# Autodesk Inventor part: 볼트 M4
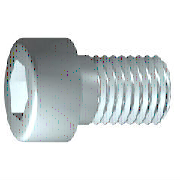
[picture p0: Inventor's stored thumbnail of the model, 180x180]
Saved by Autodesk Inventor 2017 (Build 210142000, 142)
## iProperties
IsCustomPart: 0
Created: 2015-12
Part Number: 볼트 M4
Material: 강철, 연강
Description: 6각머리 태핑 나사
Document SubType Name: Modeling
Standard: KS B 1003
Designer: mdu
Standards Organization: KS
Language: ko-KR
Size Designation: M 4 x 12
Categories: <MemberInstance><Categories><Category DisplayName="조임쇠" InternalName="e4da775c-781d-43d5-af7c-5136215cf5a6" Mnemonic="FSTN"><Category DisplayName="볼트" InternalN
Density: 7.86 g/cm^3
Mass: 2.23465 g
Surface Area: 3.30853 cm^2
Volume: 0.284306 cm^3
Appearance: 강철
Author: mdu
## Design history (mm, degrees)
sketch "스케치1"
  geometry: L1 (-1, 0)-(12, 0); L2 (12, 0)-(12, 2); L3 (12, 2)-(1.75, 2); L4 (1.75, 2)-(1.32, 2); L5 (1.32, 2)-(0, 2); L6 (0, 2)-(0, 3.5); L7 (0, 3.5)-(-4, 3.5); L8 (-4, 3.5)-(-4, 1.732); L9 (-4, 1.732)-(-2, 1.732); L10 (-2, 1.732)-(-1, 0); L11 (-7.2, 0)-(15.2, 0) reference; L12 (0, -0.7)-(0, 4.2) reference; L13 (1.75, 2)-(0, 2)
  constraints: 22 end point, 6 parallel, 2 collinear, 2 perpendicular, 1 horizontal, 1 point on line
  dimensions: "d1" = 10.25 distance from line of L3.end L2 (= GEL); "d2" = 0.42952 distance of L4.end L3.end (computed from GAL); "d3" = 4 distance between parallel lines of L8 L6 (= KOH); "d4" = 2 distance of L8.end L9.end (= INTI); "d5" = 60 deg angle of L10 L1; "d6" = 4 diameter of L3 L1 (= GD); "d7" = 4 diameter of L5 L1 (= BDM); "d8" = 3.4641 diameter of L9 L1 (= 1.1547 x SW); "d9" = 7 diameter of L7 L1 (= KOD); "d26" = 12 distance between parallel lines of L12 L2 (= NLG)
revolve "본체" sketch "스케치1" stored, may be unused: angle "d10" = 90 deg
sketch "스케치2"
  geometry: L1 (0, -4.9)-(0, 4.9) reference; L2 (-4.9, 0)-(4.9, 0) reference; L3 (1.732, 0)-(0.866, -1.5); L4 (0.866, -1.5)-(-0.866, -1.5); L5 (-0.866, -1.5)-(-1.732, 0); L6 (-1.732, 0)-(-0.866, 1.5); L7 (-0.866, 1.5)-(0.866, 1.5); L8 (0.866, 1.5)-(1.732, 0); 2 further points
  constraints: 12 end point, 1 coincident, 1 horizontal alignment, 1 point on line, 12 other
extrude "슬롯" join sketch "스케치2" stored distance "d11" = 10; taper "d12" = 0 deg
workplane "Work Plane1"
fillet "Fillet2" dims "d30" = 0.1 (= R)
body "Solid1"
fillet "모깎기1" dims "d17" = 0.4 (= RR)
feature "스레드" dims "d13" = 10.25 (= GEL), "d14" = 0
chamfer "모따기1" distance "d15" = 0.42941 (= -0.5 x SPD + 0.5 x GD); stored, may be unused: second distance "d16" = 0.42941 (= GUL), angle "d27" = 45 deg
other parameters: "GD" = 4 (= NND) [user parameter; used in 2 equation terms], "NLG" = 12 [user parameter; used in 1 equation term], "GEL" = 10.25 [user parameter; used in 2 equation terms], "KOD" = 7 [user parameter; used in 1 equation term], "KOH" = 4 [user parameter; used in 1 equation term], "INTI" = 2 [user parameter; used in 1 equation term], "GAL" = 0.42941 (= 0.61345 x PTC) [user parameter; used in 1 equation term], "GUL" = 0.42941 (= 0.61345 x PTC) [user parameter; used in 1 equation term], "BDM" = 4 (= NND) [user parameter; used in 1 equation term], "SW" = 3 [user parameter; used in 2 equation terms], "RR" = 0.4 [user parameter; used in 1 equation term], "SPD" = 3.14117 (= NND - 1.2269 x PTC) [user parameter; used in 1 equation term], "d19" = 0, "d28" = 0, "d29" = 0, "R" = 0.1 [user parameter; used in 1 equation term], "PHH" = 0.2 [user parameter], "GD1" = 3.14117 (= THREADDIA - 1.2269 x PTC) [user parameter], "THREADDIA" = 4 [user parameter; used in 1 equation term], "FAWI" = 45 deg [user parameter], "TPU" = 14.28571 (computed from PTC) [user parameter], "PTC" = 0.7 [user parameter; used in 5 equation terms], "NND" = 4 [user parameter; used in 3 equation terms], "TOA" = 30 deg [user parameter], "E0" = 3.465 (= 1.155 x SW) [user parameter]
